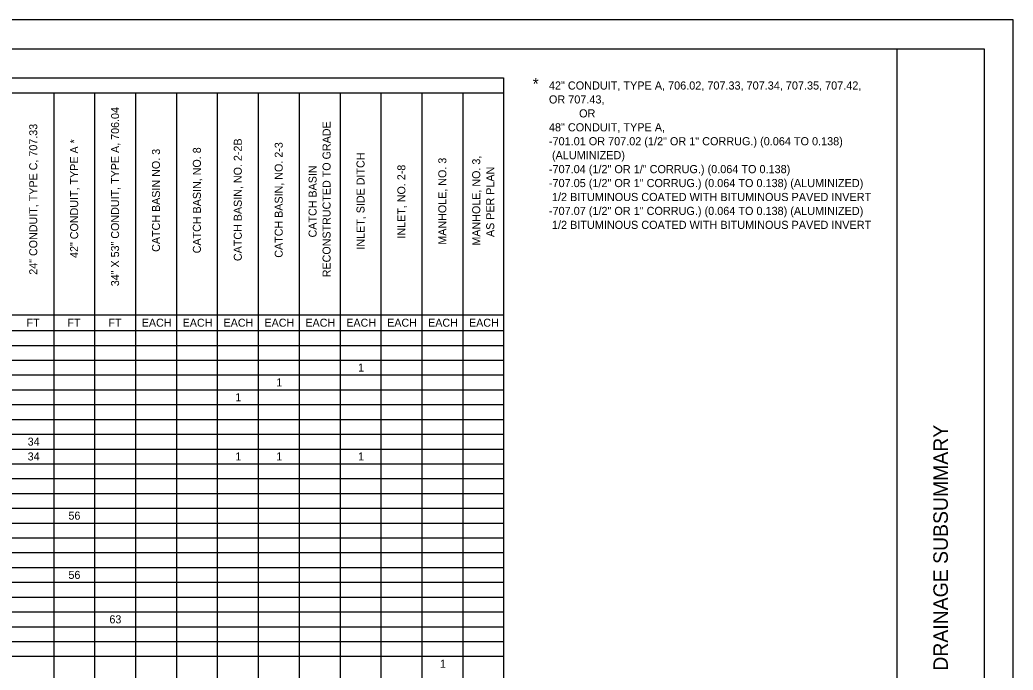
# Model space of a CAD drawing. Extents: x 0 to 34, y 0 to 22.
# Drawn here: x 16.88 to 34, y 10.8 to 22 of the extents above; entities that cross this region are included whole.
import ezdxf

# ---------------------------------------------------------------- set-up
doc = ezdxf.new("R2010")
doc.units = 0
for name, color, linetype in [('SH_Border', 7, 'Continuous'), ('SH_Cut_Line', 7, 'Continuous'), ('SH_Data', 7, 'Continuous'), ('SH_Text', 7, 'Continuous')]:
    doc.layers.add(name, color=color, linetype=linetype)

msp = doc.modelspace()

# ---------------------------------------------------------------- linework, layer by layer
at = {"layer": 'SH_Border'}
msp.add_line((32, 0.5), (32, 21.5), dxfattribs=at)
msp.add_lwpolyline([(1.5, 21.5), (33.5, 21.5), (33.5, 0.5), (1.5, 0.5)], close=True, dxfattribs=at)
at = {"layer": 'SH_Cut_Line'}
msp.add_lwpolyline([(0, 0), (34, 0), (34, 22), (0, 22)], close=True, dxfattribs=at)
at = {"layer": 'SH_Text'}
for p, q in [((7.595, 21), (25.22, 21)), ((25.22, 21), (25.22, 2.625)), ((7.595, 20.745), (25.22, 20.745)), ((17.465, 20.745), (17.465, 2.625)), ((18.17, 20.745), (18.17, 2.625)), ((18.875, 20.745), (18.875, 2.625)), ((19.58, 20.745), (19.58, 2.625)), ((20.285, 20.745), (20.285, 2.625)), ((20.99, 20.745), (20.99, 2.625)), ((21.695, 20.745), (21.695, 2.625)), ((22.4, 20.745), (22.4, 2.625)), ((23.105, 20.745), (23.105, 2.625)), ((23.81, 20.745), (23.81, 2.625)), ((24.515, 20.745), (24.515, 2.625)), ((7.595, 16.92), (25.22, 16.92)), ((7.595, 16.65), (25.22, 16.65)), ((7.595, 16.395), (25.22, 16.395)), ((7.595, 16.14), (25.22, 16.14)), ((7.595, 15.885), (25.22, 15.885)), ((7.595, 15.63), (25.22, 15.63)), ((7.595, 15.375), (25.22, 15.375)), ((7.595, 15.12), (25.22, 15.12)), ((7.595, 14.865), (25.22, 14.865)), ((7.595, 14.61), (25.22, 14.61)), ((7.595, 14.355), (25.22, 14.355)), ((7.595, 14.1), (25.22, 14.1)), ((7.595, 13.845), (25.22, 13.845)), ((7.595, 13.59), (25.22, 13.59)), ((7.595, 13.335), (25.22, 13.335)), ((7.595, 13.08), (25.22, 13.08)), ((7.595, 12.825), (25.22, 12.825)), ((7.595, 12.57), (25.22, 12.57)), ((7.595, 12.315), (25.22, 12.315)), ((7.595, 12.06), (25.22, 12.06)), ((7.595, 11.805), (25.22, 11.805)), ((7.595, 11.55), (25.22, 11.55)), ((7.595, 11.295), (25.22, 11.295)), ((7.595, 11.04), (25.22, 11.04))]:
    msp.add_line(p, q, dxfattribs=at)

# ---------------------------------------------------------------- texts
at = {"layer": 'SH_Data'}
msp.add_text('DRAINAGE SUBSUMMARY', height=0.25, rotation=90, dxfattribs=at).set_placement((32.875, 10.792))
at = {"layer": 'SH_Text'}
for s, height, p in [('*', 0.2, (25.72, 20.8)), ('42" CONDUIT, TYPE A, 706.02, 707.33, 707.34, 707.35, 707.42,', 0.14, (26, 20.8)), ('OR 707.43,', 0.14, (26, 20.56)), ('OR', 0.14, (26.52, 20.32)), ('48" CONDUIT, TYPE A,', 0.14, (26, 20.08)), ('-701.01 OR 707.02 (1/2" OR 1" CORRUG.) (0.064 TO 0.138)', 0.14, (26, 19.84)), (' (ALUMINIZED)', 0.14, (26, 19.6)), ('-707.04 (1/2" OR 1/" CORRUG.) (0.064 TO 0.138)', 0.14, (26, 19.36)), ('-707.05 (1/2" OR 1" CORRUG.) (0.064 TO 0.138) (ALUMINIZED)', 0.14, (26, 19.12)), (' 1/2 BITUMINOUS COATED WITH BITUMINOUS PAVED INVERT', 0.14, (26, 18.88)), ('-707.07 (1/2" OR 1" CORRUG.) (0.064 TO 0.138) (ALUMINIZED)', 0.14, (26, 18.64)), (' 1/2 BITUMINOUS COATED WITH BITUMINOUS PAVED INVERT', 0.14, (26, 18.4)), ('FT', 0.138, (16.998, 16.716)), ('FT', 0.138, (17.703, 16.716)), ('FT', 0.138, (18.408, 16.716)), ('EACH', 0.138, (18.983, 16.716)), ('EACH', 0.138, (19.688, 16.716)), ('EACH', 0.138, (20.393, 16.716)), ('EACH', 0.138, (21.098, 16.716)), ('EACH', 0.138, (21.803, 16.716)), ('EACH', 0.138, (22.508, 16.716)), ('EACH', 0.138, (23.213, 16.716)), ('EACH', 0.138, (23.918, 16.716)), ('EACH', 0.138, (24.623, 16.716)), ('1', 0.138, (22.711, 15.944)), ('1', 0.138, (21.301, 15.688)), ('1', 0.138, (20.596, 15.433)), ('34', 0.138, (17.017, 14.668)), ('34', 0.138, (17.017, 14.413)), ('1', 0.138, (20.596, 14.413)), ('1', 0.138, (21.301, 14.413)), ('1', 0.138, (22.711, 14.413)), ('56', 0.138, (17.72, 13.393)), ('56', 0.138, (17.72, 12.373)), ('63', 0.138, (18.426, 11.608)), ('1', 0.138, (24.121, 10.843))]:
    msp.add_text(s, height=height, dxfattribs=at).set_placement(p)
for s, p in [(' 34" X 53" CONDUIT, TYPE A, 706.04', (18.592, 17.362)), ('24" CONDUIT, TYPE C, 707.33', (17.182, 17.611)), ('RECONSTRUCTED TO GRADE', (22.237, 17.567)), (' 42" CONDUIT, TYPE A *', (17.887, 17.849)), ('CATCH BASIN, NO. 2-2B', (20.707, 17.846)), ('CATCH BASIN, NO. 2-3', (21.412, 17.904)), ('CATCH BASIN NO. 3', (19.297, 18.005)), ('CATCH BASIN, NO. 8', (20.002, 17.98)), ('INLET, SIDE DITCH', (22.822, 18.044)), ('MANHOLE, NO. 3', (24.232, 18.129)), ('MANHOLE, NO. 3,', (24.816, 18.113)), ('CATCH BASIN', (21.996, 18.253)), ('INLET, NO. 2-8', (23.526, 18.234)), ('AS PER PLAN', (25.057, 18.261))]:
    msp.add_text(s, height=0.138, rotation=90, dxfattribs=at).set_placement(p)

doc.saveas('drawing.dxf')
